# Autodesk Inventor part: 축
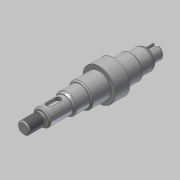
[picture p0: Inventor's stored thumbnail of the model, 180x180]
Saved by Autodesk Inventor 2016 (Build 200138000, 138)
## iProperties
Created: 2019-09
Part Number: 축
Material: 강철, 연강
Document SubType Name: Modeling
Designer: mduedu
Density: 7.86 g/cm^3
Mass: 210.278 g
Surface Area: 69.4769 cm^2
Volume: 26.7529 cm^3
Appearance: 강철
Author: mduedu
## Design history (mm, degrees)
sketch "스케치1"
  geometry: L1 (0, 0)-(15, 0); L2 (15, 0)-(15, 5); L3 (15, 5)-(0, 5); L4 (0, 5)-(0, 0); L5 (15, 0)-(34, 0); L6 (34, 0)-(34, 7); L7 (34, 7)-(15, 7); L8 (15, 7)-(15, 0); L9 (34, 0)-(47, 0); L10 (47, 0)-(47, 8.5); L11 (47, 8.5)-(34, 8.5); L12 (34, 8.5)-(34, 0); L13 (47, 0)-(63, 0); L14 (63, 0)-(63, 10); L15 (63, 10)-(47, 10); L16 (47, 10)-(47, 0); L17 (63, 0)-(75, 0); L18 (75, 0)-(75, 13.5); L19 (75, 13.5)-(63, 13.5); L20 (63, 13.5)-(63, 0); L21 (75, 0)-(90, 0); L22 (90, 0)-(90, 10); L23 (90, 10)-(75, 10); L24 (75, 10)-(75, 0); L25 (90, 0)-(102, 0); L26 (102, 0)-(102, 8.5); L27 (102, 8.5)-(90, 8.5); L28 (90, 8.5)-(90, 0); L29 (102, 0)-(111, 0); L30 (111, 0)-(111, 5.5); L31 (111, 5.5)-(102, 5.5); L32 (102, 5.5)-(102, 0)
  constraints: 64 end point, 16 parallel, 8 horizontal, 8 perpendicular
  dimensions: "d0" = 111 distance between parallel lines of L30 L4; "d2" = 15 distance of L2.end L3.end; "d3" = 19 distance of L6.end L7.end; "d4" = 12 distance of L18.end L19.end; "d5" = 15 distance of L22.end L23.end; "d6" = 12 distance of L26.end L27.end; "d7" = 9 distance of L30.end L31.end; "d8" = 16 distance of L14.end L15.end; "d9" = 10 diameter of L3 L1; "d10" = 14 diameter of L7 L5; "d11" = 17 diameter of L11 L9; "d12" = 20 diameter of L15 L13; "d13" = 27 diameter of L19 L17; "d14" = 20 diameter of L23 L21; "d15" = 17 diameter of L27 L25; "d16" = 11 diameter of L31 L29
revolve "회전1" sketch "스케치1" stored, may be unused: angle "d17" = 90 deg
sketch "스케치2"
  geometry: L1 (0, -5)-(0, 5) reference; L2 (0, 5)-(15, 5) reference; L3 (15, 5)-(15, 7) reference; L4 (15, 7)-(34, 7) reference; L5 (34, 7)-(34, 8.5) reference; L6 (34, 8.5)-(47, 8.5) reference; L7 (47, 8.5)-(47, 10) reference; L8 (47, 10)-(63, 10) reference; L9 (63, 10)-(63, 13.5) reference; L10 (63, 13.5)-(75, 13.5) reference; L11 (75, 13.5)-(75, 10) reference; L12 (75, 10)-(90, 10) reference; L13 (90, 10)-(90, 8.5) reference; L14 (90, 8.5)-(102, 8.5) reference; L15 (102, 8.5)-(102, 5.5) reference; L16 (102, 5.5)-(111, 5.5) reference; L17 (111, 5.5)-(111, -5.5) reference; L18 (111, -5.5)-(102, -5.5) reference; L19 (102, -5.5)-(102, -8.5) reference; L20 (102, -8.5)-(90, -8.5) reference; L21 (90, -8.5)-(90, -10) reference; L22 (90, -10)-(75, -10) reference; L23 (75, -10)-(75, -13.5) reference; L24 (75, -13.5)-(63, -13.5) reference; L25 (63, -13.5)-(63, -10) reference; L26 (63, -10)-(47, -10) reference; L27 (47, -10)-(47, -8.5) reference; L28 (47, -8.5)-(34, -8.5) reference; L29 (34, -8.5)-(34, -7) reference; L30 (34, -7)-(15, -7) reference; L31 (15, -7)-(15, -5) reference; L32 (15, -5)-(0, -5) reference; L33 (0, 0)-(111, 0); L34 (15, 5)-(12.014, 5); L35 (13.4, 4.2)-(15, 4.2); L36 (15, 4.2)-(15, 5); L37 (12.014, 5)-(13.4, 4.2)
  constraints: 10 end point, 1 horizontal, 1 midpoint, 1 parallel, 1 vertical
  dimensions: "d18" = 30 deg angle of L2 L37; "d19" = 8.4 diameter of L35 L33; "d21" = 2.986 distance from line of L34.end L36
revolve "회전2" sketch "스케치2" stored, may be unused: angle "d22" = 90 deg
fillet "모깎기1" dims "d23" = 0.6
feature "스레드1" dims "d24" = 10, "d25" = 0
chamfer "모따기1" distance "d26" = 1; stored, may be unused: second distance "d27" = 2, angle "d28" = 45 deg
chamfer "모따기2" distance "d29" = 1; stored, may be unused: second distance "d30" = 2, angle "d31" = 45 deg
chamfer "모따기3" distance "d32" = 1.819; stored, may be unused: second distance "d33" = 2, angle "d34" = 30 deg
fillet "모깎기2" dims "d35" = 2
chamfer "모따기4" distance "d36" = 1; stored, may be unused: second distance "d37" = 2, angle "d38" = 30 deg
fillet "모깎기3" dims "d39" = 0.3
chamfer "모따기5" distance "d40" = 1; stored, may be unused: second distance "d41" = 2, angle "d42" = 30 deg
chamfer "모따기6" distance "d43" = 1.819; stored, may be unused: second distance "d44" = 2, angle "d45" = 30 deg
chamfer "모따기7" distance "d46" = 0.5; stored, may be unused: second distance "d47" = 2, angle "d48" = 30 deg
fillet "모깎기4" dims "d49" = 2
node "작업 평면1"
sketch "스케치3" dims "d51" = 12
  geometry: L1 (3, -2.5)-(-4, -2.5); L2 (-4, -2.5)-(-4, 2.5); L3 (-4, 2.5)-(3, 2.5); L4 (3, 2.5)-(3, -2.5); L5 (-9.5, 7.45)-(-9.5, -7.45) reference; 3 further points
  constraints: 8 end point, 2 midpoint, 2 parallel, 2 vertical alignment, 1 horizontal, 1 horizontal alignment, 1 perpendicular, 4 other
  dimensions: "d50" = 3 dimension on L5; "d52" = 5 distance between parallel lines of L3 L1
extrude "돌출1" cut sketch "스케치3" distance "d53" = 3; taper "d54" = 0 deg
node "작업 평면3"
sketch "스케치4"
  geometry: L1 (-4.5, -5)-(-4.5, 5) reference; L2 (-4.5, -2)-(1.5, -2); L3 (1.5, -2)-(1.5, 2); L4 (1.5, 2)-(-4.5, 2); L5 (-4.5, 2)-(-4.5, -2); 3 further points
  constraints: 8 end point, 2 horizontal alignment, 2 midpoint, 2 parallel, 1 horizontal, 1 perpendicular, 1 point on line, 1 vertical alignment, 2 other
  dimensions: "d55" = 4 distance between parallel lines of L4 L2; "d57" = 8 dimension on L1
extrude "돌출2" cut sketch "스케치4" distance "d58" = 2.5; taper "d59" = 0 deg
sketch "스케치5"
  geometry: A1 r 5.5 centre (2, -3) between (0, 2.123) and (4, 2.123) reference; 2 further points
  constraints: 1 point on circle
hole "구멍1" sketch "스케치5" at (2, -8.5) diameter "d60" = 2.459; stored, may be unused: countersink angle "d64" = 90 deg, drill point angle "d66" = 118 deg; dims "d61" = 6, "d62" = 4, "d63" = 2, "d65" = 5
node "솔리드1"
node "절단 모서리 투영1"
